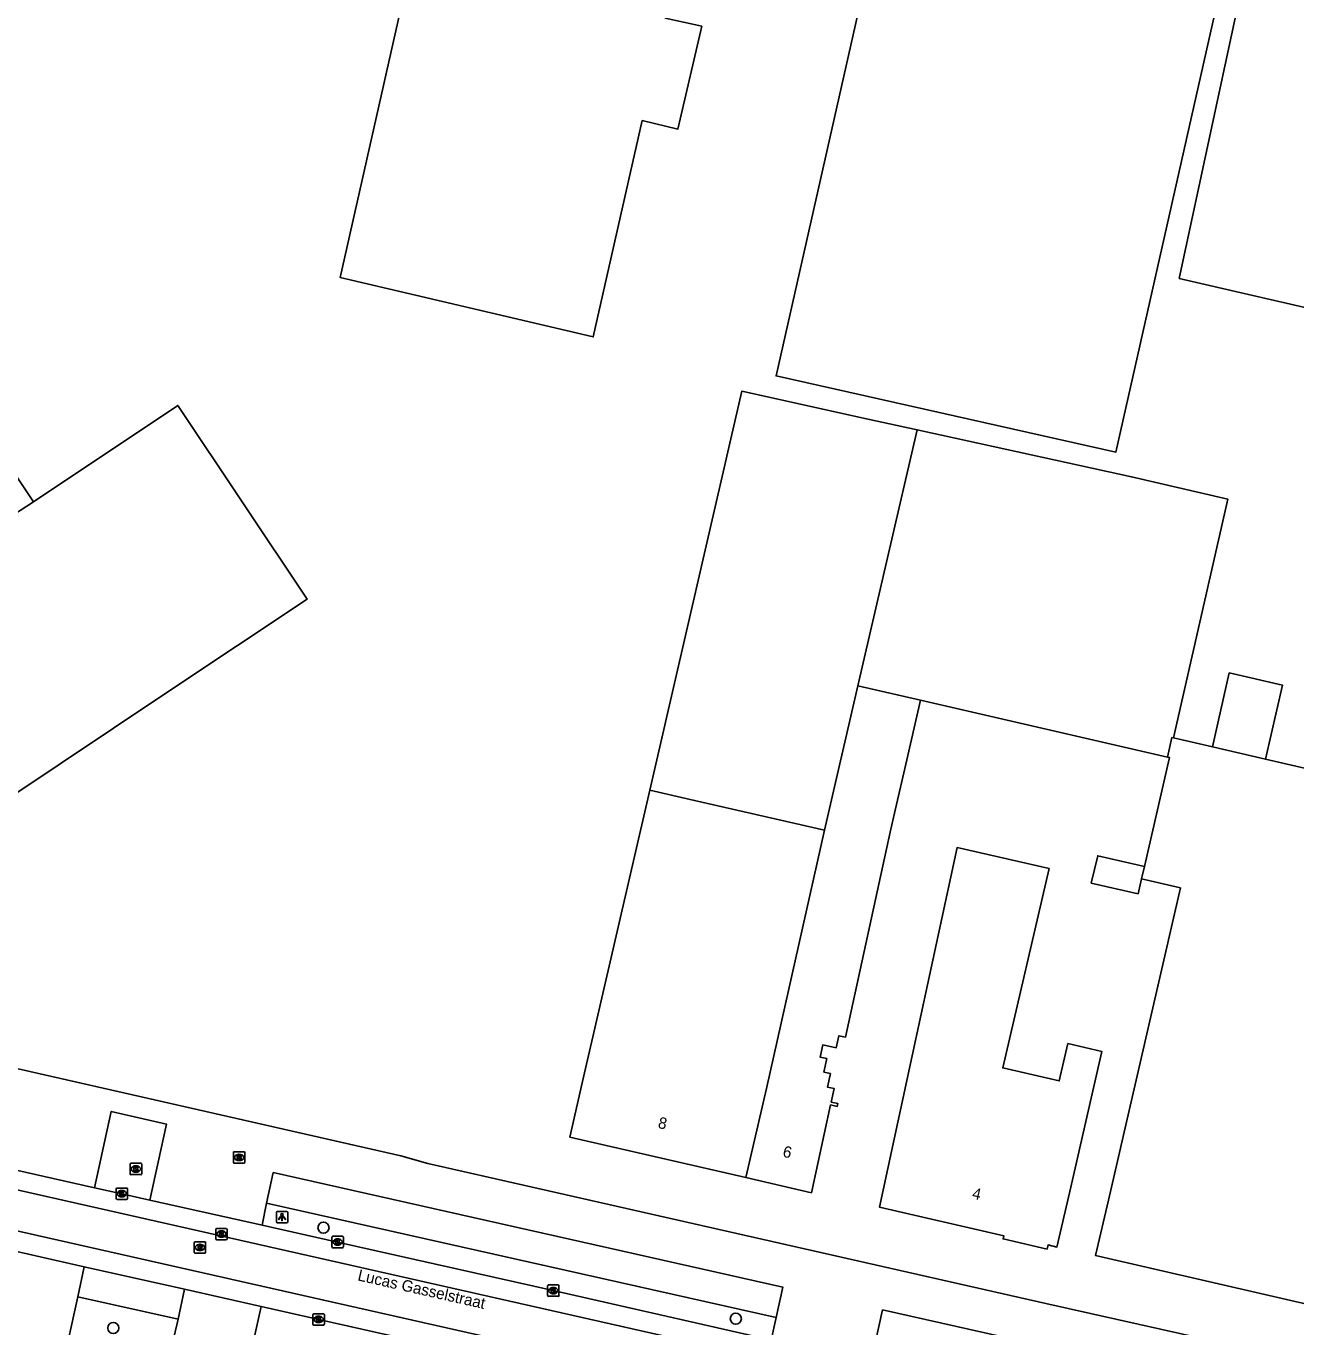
# Model space of a CAD drawing. Extents: x 161771 to 163125, y 382479 to 383177.
# Drawn here: x 162363.8 to 162475.6, y 382859.4 to 382973.9 of the extents above; entities that cross this region are included whole.
import ezdxf

# ---------------------------------------------------------------- set-up
doc = ezdxf.new("R2010")
doc.units = 0
for name, color, linetype in [('IMGEO_Boom', 7, 'Continuous'), ('IMGEO_Kolk', 7, 'Continuous'), ('IMGEO_Lichtpunt', 7, 'Continuous'), ('IMGEO_Openbare_ruimte_label', 7, 'Continuous'), ('IMGEO_Pand', 7, 'Continuous'), ('IMGEO_Pand_nummerreeks', 7, 'Continuous'), ('IMGEO_Parkeervlak_open', 7, 'Continuous'), ('IMGEO_Rijbaan_lokaal_gesloten', 7, 'Continuous'), ('IMGEO_Rioolput', 7, 'Continuous'), ('IMGEO_Voetpad_open', 7, 'Continuous')]:
    doc.layers.add(name, color=color, linetype=linetype)

msp = doc.modelspace()

# ---------------------------------------------------------------- linework, layer by layer
at = {"layer": 'IMGEO_Boom'}
for centre in [(162389.99, 382868.18), (162371.49, 382859.35), (162426.28, 382860.17)]:
    msp.add_circle(centre, 0.489, dxfattribs=at)
at = {"layer": 'IMGEO_Kolk'}
for p, q in [((162372.99, 382872.92), (162372.99, 382873.77)), ((162373.06, 382873.85), (162373.91, 382873.85)), ((162373.47, 382873.63), (162373.5, 382873.63)), ((162373.99, 382873.77), (162373.99, 382872.92)), ((162373.91, 382872.85), (162373.06, 382872.85)), ((162373.5, 382873.07), (162373.47, 382873.07)), ((162371.74, 382870.74), (162371.74, 382871.6)), ((162371.82, 382871.67), (162372.67, 382871.67)), ((162372.23, 382871.45), (162372.25, 382871.45)), ((162372.74, 382871.6), (162372.74, 382870.74)), ((162372.67, 382870.67), (162371.82, 382870.67)), ((162372.25, 382870.89), (162372.23, 382870.89)), ((162390.74, 382866.49), (162390.74, 382867.34)), ((162390.81, 382867.42), (162391.67, 382867.42)), ((162391.23, 382867.2), (162391.25, 382867.2)), ((162391.25, 382866.64), (162391.23, 382866.64)), ((162391.74, 382867.34), (162391.74, 382866.49)), ((162391.67, 382866.42), (162390.81, 382866.42)), ((162409.8, 382863.14), (162410.65, 382863.14)), ((162409.72, 382862.21), (162409.72, 382863.06)), ((162410.65, 382862.14), (162409.8, 382862.14)), ((162410.21, 382862.92), (162410.23, 382862.92)), ((162410.23, 382862.36), (162410.21, 382862.36)), ((162410.72, 382863.06), (162410.72, 382862.21)), ((162389.06, 382859.68), (162389.06, 382860.53)), ((162389.14, 382860.61), (162389.99, 382860.61)), ((162389.55, 382860.39), (162389.58, 382860.39)), ((162389.57, 382859.83), (162389.55, 382859.83)), ((162390.07, 382860.53), (162390.07, 382859.68)), ((162389.99, 382859.61), (162389.14, 382859.61))]:
    msp.add_line(p, q, dxfattribs=at)
for points in [[(162372.99, 382872.92), (162372.99, 382873.77)], [(162373.06, 382873.85), (162373.91, 382873.85)], [(162373.31, 382873.55), (162373.43, 382873.55), (162373.43, 382873.39), (162373.56, 382873.55), (162373.72, 382873.55), (162373.58, 382873.4), (162373.73, 382873.15), (162373.58, 382873.15), (162373.49, 382873.31), (162373.43, 382873.24), (162373.43, 382873.15), (162373.31, 382873.15), (162373.31, 382873.55)], [(162373.99, 382873.77), (162373.99, 382872.92)], [(162373.91, 382872.85), (162373.06, 382872.85)], [(162371.74, 382870.74), (162371.74, 382871.6)], [(162371.82, 382871.67), (162372.67, 382871.67)], [(162372.06, 382871.37), (162372.19, 382871.37), (162372.19, 382871.22), (162372.31, 382871.37), (162372.48, 382871.37), (162372.33, 382871.22), (162372.49, 382870.97), (162372.33, 382870.97), (162372.25, 382871.14), (162372.19, 382871.07), (162372.19, 382870.97), (162372.06, 382870.97), (162372.06, 382871.37)], [(162372.74, 382871.6), (162372.74, 382870.74)], [(162372.67, 382870.67), (162371.82, 382870.67)], [(162390.74, 382866.49), (162390.74, 382867.34)], [(162390.81, 382867.42), (162391.67, 382867.42)], [(162391.06, 382867.12), (162391.18, 382867.12), (162391.18, 382866.96), (162391.31, 382867.12), (162391.48, 382867.12), (162391.33, 382866.97), (162391.48, 382866.72), (162391.33, 382866.72), (162391.25, 382866.88), (162391.18, 382866.81), (162391.18, 382866.72), (162391.06, 382866.72), (162391.06, 382867.12)], [(162391.74, 382867.34), (162391.74, 382866.49)], [(162391.67, 382866.42), (162390.81, 382866.42)], [(162409.8, 382863.14), (162410.65, 382863.14)], [(162409.72, 382862.21), (162409.72, 382863.06)], [(162410.65, 382862.14), (162409.8, 382862.14)], [(162410.04, 382862.84), (162410.17, 382862.84), (162410.17, 382862.69), (162410.29, 382862.84), (162410.46, 382862.84), (162410.31, 382862.69), (162410.47, 382862.44), (162410.31, 382862.44), (162410.23, 382862.6), (162410.17, 382862.53), (162410.17, 382862.44), (162410.04, 382862.44), (162410.04, 382862.84)], [(162410.72, 382863.06), (162410.72, 382862.21)], [(162389.06, 382859.68), (162389.06, 382860.53)], [(162389.14, 382860.61), (162389.99, 382860.61)], [(162389.38, 382860.31), (162389.51, 382860.31), (162389.51, 382860.15), (162389.64, 382860.31), (162389.8, 382860.31), (162389.66, 382860.16), (162389.81, 382859.91), (162389.66, 382859.91), (162389.57, 382860.07), (162389.51, 382860), (162389.51, 382859.91), (162389.38, 382859.91), (162389.38, 382860.31)], [(162390.07, 382860.53), (162390.07, 382859.68)], [(162389.99, 382859.61), (162389.14, 382859.61)]]:
    msp.add_lwpolyline(points, dxfattribs=at)
for centre, start, end in [((162373.06, 382873.77), 91.552, 178.448), ((162373.06, 382873.77), 91.552, 178.448), ((162373.91, 382873.77), 1.552, 88.448), ((162373.91, 382873.77), 1.552, 88.448), ((162373.06, 382872.92), 181.552, 268.448), ((162373.06, 382872.92), 181.552, 268.448), ((162373.91, 382872.92), 271.552, 358.448), ((162373.91, 382872.92), 271.552, 358.448), ((162371.82, 382871.6), 91.552, 178.448), ((162371.82, 382871.6), 91.552, 178.448), ((162372.67, 382871.6), 1.552, 88.448), ((162372.67, 382871.6), 1.552, 88.448), ((162371.82, 382870.75), 181.552, 268.448), ((162371.82, 382870.75), 181.552, 268.448), ((162372.67, 382870.75), 271.552, 358.448), ((162372.67, 382870.75), 271.552, 358.448), ((162390.82, 382867.34), 91.552, 178.448), ((162390.82, 382867.34), 91.552, 178.448), ((162391.66, 382867.34), 1.552, 88.448), ((162391.66, 382867.34), 1.552, 88.448), ((162390.82, 382866.49), 181.552, 268.448), ((162390.82, 382866.49), 181.552, 268.448), ((162391.66, 382866.49), 271.552, 358.448), ((162391.66, 382866.49), 271.552, 358.448), ((162409.8, 382863.06), 91.552, 178.448), ((162409.8, 382863.06), 91.552, 178.448), ((162410.65, 382863.06), 1.552, 88.448), ((162410.65, 382863.06), 1.552, 88.448), ((162409.8, 382862.21), 181.552, 268.448), ((162409.8, 382862.21), 181.552, 268.448), ((162410.65, 382862.21), 271.552, 358.448), ((162410.65, 382862.21), 271.552, 358.448), ((162389.14, 382860.53), 91.552, 178.448), ((162389.14, 382860.53), 91.552, 178.448), ((162389.14, 382859.68), 181.552, 268.448), ((162389.14, 382859.68), 181.552, 268.448), ((162389.99, 382860.53), 1.552, 88.448), ((162389.99, 382860.53), 1.552, 88.448), ((162389.99, 382859.68), 271.552, 358.448), ((162389.99, 382859.68), 271.552, 358.448)]:
    msp.add_arc(centre, 0.0765, start, end, dxfattribs=at)
for centre, major_axis, ratio, start_param, end_param in [((162373.47, 382873.35), (-0.387, 0.002), 0.722429, 4.712389, 7.853982), ((162373.5, 382873.35), (-0.39, 0.002), 0.717154, 1.570796, 4.712389), ((162372.23, 382871.17), (-0.387, 0.002), 0.722429, 4.712389, 7.853982), ((162372.25, 382871.17), (-0.39, 0.002), 0.717154, 1.570796, 4.712389), ((162391.23, 382866.92), (-0.387, 0.002), 0.722429, 4.712389, 7.853982), ((162391.25, 382866.92), (-0.39, 0.002), 0.717154, 1.570796, 4.712389), ((162410.21, 382862.64), (-0.387, 0.002), 0.722429, 4.712389, 7.853982), ((162410.23, 382862.64), (-0.39, 0.002), 0.717154, 1.570796, 4.712389), ((162389.55, 382860.11), (-0.387, 0.002), 0.722429, 4.712389, 7.853982), ((162389.58, 382860.11), (-0.39, 0.002), 0.717154, 1.570796, 4.712389)]:
    msp.add_ellipse(centre, major_axis=major_axis, ratio=ratio, start_param=start_param, end_param=end_param, dxfattribs=at)
at = {"layer": 'IMGEO_Lichtpunt'}
for p, q in [((162385.85, 382869.52), (162385.85, 382868.71)), ((162385.85, 382869.52), (162385.85, 382868.71)), ((162386.75, 382869.62), (162385.94, 382869.62)), ((162386.75, 382869.62), (162385.94, 382869.62)), ((162386.85, 382868.71), (162386.85, 382869.52)), ((162386.85, 382868.71), (162386.85, 382869.52)), ((162385.94, 382868.62), (162386.75, 382868.62)), ((162385.94, 382868.62), (162386.75, 382868.62))]:
    msp.add_line(p, q, dxfattribs=at)
for points in [[(162386.22, 382869.18), (162386.26, 382869.16), (162386.07, 382868.89), (162386.04, 382868.92), (162386.22, 382869.18)], [(162386.32, 382869.14), (162386.37, 382869.14), (162386.37, 382868.81), (162386.32, 382868.81), (162386.32, 382869.14)], [(162386.43, 382869.16), (162386.47, 382869.18), (162386.66, 382868.92), (162386.62, 382868.89), (162386.43, 382869.16)]]:
    msp.add_lwpolyline(points, dxfattribs=at)
msp.add_circle((162386.35, 382869.32), 0.0994, dxfattribs=at)
for centre, start, end in [((162385.94, 382869.52), 90, 180), ((162385.94, 382869.52), 90, 180), ((162386.75, 382869.52), 0, 90), ((162386.75, 382869.52), 0, 90), ((162385.94, 382868.71), 180, 270), ((162385.94, 382868.71), 180, 270), ((162386.75, 382868.71), 270, 0), ((162386.75, 382868.71), 270, 360)]:
    msp.add_arc(centre, 0.0946, start, end, dxfattribs=at)
at = {"layer": 'IMGEO_Pand'}
for points in [[(162427.74, 383000.41), (162426.87, 382996.7), (162425.17, 382997.1), (162420.34, 382975.79), (162420.07, 382974.64), (162423.28, 382973.91), (162421.18, 382964.87), (162418.05, 382965.61), (162413.73, 382946.58), (162391.46, 382951.81), (162400.65, 382992.52), (162403.25, 382991.93), (162402.89, 382990.34), (162418.4, 382986.84), (162421.3, 382999.68), (162424.89, 382998.86), (162424.99, 382999.26), (162425.37, 383000.91)], [(162470.51, 382991.08), (162469.41, 382986.14), (162470.87, 382985.85), (162459.74, 382936.44), (162429.83, 382943.14), (162441.13, 382993.19), (162444.44, 382992.42), (162445.17, 382995.46), (162446.64, 382995.17), (162446.92, 382996.39)], [(162525.72, 382978.26), (162520.64, 382955.82), (162498.45, 382960.84), (162497.41, 382956.34), (162485.74, 382959.03), (162483.11, 382947.62), (162465.31, 382951.72), (162471.68, 382981.36), (162471.87, 382981.32), (162477.88, 382979.93)], [(162338.5, 382915.18), (162328.22, 382932.53), (162353.13, 382949.04), (162364.46, 382932.07)], [(162418.71, 382906.68), (162426.8, 382941.79), (162438.06, 382939.32), (162442.24, 382938.4)], [(162364.46, 382932.07), (162377.17, 382940.55), (162388.55, 382923.49), (162376.12, 382915.21), (162352.87, 382899.71), (162350.05, 382897.83), (162348.8, 382899.71), (162338.69, 382914.86), (162338.5, 382915.18)], [(162437.02, 382915.88), (162442.24, 382938.4)], [(162442.24, 382938.4), (162461.11, 382934.27), (162469.58, 382932.31), (162464.8, 382911.28)], [(162364.46, 382932.07), (162338.5, 382915.18)], [(162472.91, 382909.42), (162474.39, 382915.94), (162469.71, 382917.01), (162468.23, 382910.49)], [(162437.02, 382915.88), (162434.08, 382903.17)], [(162442.53, 382914.61), (162437.02, 382915.88)], [(162442.53, 382914.61), (162441.42, 382909.74), (162440.17, 382904.28), (162439.87, 382902.98), (162435.93, 382884.96), (162435.35, 382885.08), (162435.12, 382884.02), (162433.94, 382884.27), (162433.7, 382883.19), (162434.29, 382883.06), (162434.03, 382881.87), (162434.61, 382881.74), (162434.35, 382880.55), (162434.94, 382880.42), (162434.68, 382879.23), (162435.27, 382879.1), (162435.21, 382878.86), (162434.63, 382878.99), (162432.94, 382871.26), (162427.17, 382872.59)], [(162464.28, 382909.6), (162442.53, 382914.61)], [(162464.8, 382911.28), (162464.67, 382911.31), (162464.28, 382909.6)], [(162468.23, 382910.49), (162464.8, 382911.28)], [(162468.23, 382910.49), (162472.91, 382909.42)], [(162461.99, 382898.88), (162465.41, 382898.09), (162459.08, 382870.6), (162457.95, 382865.73), (162498.57, 382856.37), (162500, 382862.8), (162508.56, 382901.23), (162503.68, 382902.33), (162500, 382903.18), (162472.91, 382909.42)], [(162464.28, 382909.6), (162464.46, 382909.56), (162462.24, 382899.97)], [(162427.17, 382872.59), (162411.68, 382876.16), (162412.8, 382881.04), (162418.71, 382906.68)], [(162434.08, 382903.17), (162422.66, 382905.78), (162418.71, 382906.68)], [(162434.08, 382903.17), (162428.98, 382880.42), (162427.17, 382872.59)], [(162453.85, 382899.78), (162449.78, 382882.24), (162454.75, 382881.1), (162455.51, 382884.38), (162458.51, 382883.68), (162455.67, 382871.36), (162454.55, 382866.48), (162453.76, 382866.67), (162453.68, 382866.3), (162449.81, 382867.19), (162449.87, 382867.47), (162438.92, 382869.99), (162439.98, 382874.88), (162445.76, 382901.63), (162453.85, 382899.78)], [(162461.99, 382898.88), (162461.69, 382897.57), (162457.57, 382898.51), (162458.13, 382900.91), (162462.24, 382899.97)], [(162462.24, 382899.97), (162461.99, 382898.88)]]:
    msp.add_lwpolyline(points, dxfattribs=at)
at = {"layer": 'IMGEO_Parkeervlak_open'}
for points in [[(162384.98, 382870.35), (162429.82, 382860.29)], [(162377.19, 382860.12), (162368.36, 382862.09)]]:
    msp.add_lwpolyline(points, dxfattribs=at)
at = {"layer": 'IMGEO_Rijbaan_lokaal_gesloten'}
for points in [[(162369.84, 382871.7), (162360.06, 382873.9), (162359.13, 382874.16)], [(162522.17, 382835.64), (162521.01, 382835.9), (162466.66, 382848.1), (162359.48, 382872.3)], [(162374.72, 382870.6), (162372.24, 382871.17), (162369.84, 382871.7)], [(162384.59, 382868.39), (162374.72, 382870.6)], [(162521.18, 382832.27), (162495.04, 382838.14), (162484.83, 382840.43), (162390.02, 382861.8), (162355.96, 382869.49)], [(162429.38, 382858.29), (162427.26, 382858.79), (162410.22, 382862.64), (162391.24, 382866.92), (162384.59, 382868.39)], [(162360.78, 382866.57), (162368.94, 382864.74)], [(162368.94, 382864.74), (162377.77, 382862.76)], [(162377.77, 382862.76), (162384.5, 382861.24)], [(162384.5, 382861.24), (162389.57, 382860.11), (162408.51, 382855.84), (162414.43, 382854.5)]]:
    msp.add_lwpolyline(points, dxfattribs=at)
at = {"layer": 'IMGEO_Rioolput'}
for p, q in [((162382.07, 382873.94), (162382.07, 382874.79)), ((162382.14, 382874.86), (162382.99, 382874.86)), ((162382.55, 382874.64), (162382.58, 382874.64)), ((162383.07, 382874.79), (162383.07, 382873.94)), ((162382.99, 382873.86), (162382.14, 382873.86)), ((162382.58, 382874.08), (162382.55, 382874.08)), ((162380.51, 382867.19), (162380.51, 382868.04)), ((162380.59, 382868.12), (162381.44, 382868.12)), ((162381, 382867.9), (162381.02, 382867.9)), ((162381.51, 382868.04), (162381.51, 382867.19)), ((162378.62, 382866.01), (162378.62, 382866.86)), ((162378.7, 382866.94), (162379.55, 382866.94)), ((162379.11, 382866.72), (162379.13, 382866.72)), ((162379.62, 382866.86), (162379.62, 382866.01)), ((162381.44, 382867.12), (162380.59, 382867.12)), ((162381.02, 382867.34), (162381, 382867.34)), ((162379.55, 382865.94), (162378.7, 382865.94)), ((162379.13, 382866.16), (162379.11, 382866.16))]:
    msp.add_line(p, q, dxfattribs=at)
for points in [[(162382.07, 382873.94), (162382.07, 382874.79)], [(162382.14, 382874.86), (162382.99, 382874.86)], [(162382.65, 382874.56), (162382.4, 382874.56), (162382.4, 382874.16)], [(162383.07, 382874.79), (162383.07, 382873.94)], [(162382.99, 382873.86), (162382.14, 382873.86)], [(162382.4, 382874.16), (162382.53, 382874.16), (162382.53, 382874.32), (162382.54, 382874.32)], [(162382.58, 382874.48), (162382.53, 382874.48), (162382.53, 382874.4)], [(162382.53, 382874.4), (162382.58, 382874.4)], [(162382.58, 382874.29), (162382.66, 382874.16), (162382.79, 382874.16), (162382.73, 382874.29)], [(162380.51, 382867.19), (162380.51, 382868.04)], [(162380.59, 382868.12), (162381.44, 382868.12)], [(162381.1, 382867.81), (162380.85, 382867.82), (162380.85, 382867.42)], [(162381.03, 382867.74), (162380.97, 382867.74), (162380.97, 382867.65)], [(162380.97, 382867.65), (162381.02, 382867.65)], [(162381.51, 382868.04), (162381.51, 382867.19)], [(162378.62, 382866.01), (162378.62, 382866.86)], [(162378.7, 382866.94), (162379.55, 382866.94)], [(162379.21, 382866.63), (162378.96, 382866.64), (162378.96, 382866.24)], [(162379.14, 382866.56), (162379.08, 382866.56), (162379.08, 382866.47)], [(162379.62, 382866.86), (162379.62, 382866.01)], [(162381.44, 382867.12), (162380.59, 382867.12)], [(162380.85, 382867.42), (162380.97, 382867.42), (162380.97, 382867.58), (162380.98, 382867.58)], [(162381.03, 382867.55), (162381.1, 382867.42), (162381.24, 382867.42), (162381.18, 382867.54)], [(162379.55, 382865.94), (162378.7, 382865.94)], [(162378.96, 382866.24), (162379.08, 382866.24), (162379.08, 382866.4), (162379.09, 382866.4)], [(162379.08, 382866.47), (162379.13, 382866.47)], [(162379.14, 382866.37), (162379.21, 382866.24), (162379.35, 382866.24), (162379.29, 382866.36)]]:
    msp.add_lwpolyline(points, dxfattribs=at)
for centre, radius, start, end in [((162382.14, 382874.79), 0.0765, 91.552, 178.448), ((162382.14, 382874.79), 0.0765, 91.552, 178.448), ((162382.65, 382874.45), 0.109, 350.3612, 89.416), ((162382.99, 382874.79), 0.0765, 1.552, 88.448), ((162382.99, 382874.79), 0.0765, 1.552, 88.448), ((162382.14, 382873.94), 0.0765, 181.552, 268.448), ((162382.14, 382873.94), 0.0765, 181.552, 268.448), ((162382.54, 382874.27), 0.0533, 26.0293, 88.6989), ((162382.59, 382874.38), 0.0964, 77.0061, 93.1865), ((162382.56, 382874.59), 0.19, 274.7715, 282.9687), ((162382.6, 382874.44), 0.0378, 276.6634, 79.6772), ((162382.65, 382874.45), 0.112, 277.5842, 350.9817), ((162382.64, 382874.23), 0.108, 29.5134, 73.7905), ((162382.99, 382873.94), 0.0765, 271.552, 358.448), ((162382.99, 382873.94), 0.0765, 271.552, 358.448), ((162380.59, 382868.04), 0.0765, 91.552, 178.448), ((162380.59, 382868.04), 0.0765, 91.552, 178.448), ((162381.01, 382867.84), 0.19, 274.7715, 282.9687), ((162381.03, 382867.64), 0.0964, 77.0061, 93.1865), ((162381.05, 382867.7), 0.0378, 276.6634, 79.6772), ((162381.1, 382867.71), 0.109, 350.3612, 89.416), ((162381.1, 382867.7), 0.112, 277.5842, 350.9817), ((162381.44, 382868.04), 0.0765, 1.552, 88.448), ((162381.44, 382868.04), 0.0765, 1.552, 88.448), ((162378.7, 382866.86), 0.0765, 91.552, 178.448), ((162378.7, 382866.86), 0.0765, 91.552, 178.448), ((162379.14, 382866.46), 0.0964, 77.0061, 93.1865), ((162379.16, 382866.52), 0.0378, 276.6634, 79.6772), ((162379.21, 382866.52), 0.109, 350.3612, 89.416), ((162379.21, 382866.52), 0.112, 277.5842, 350.9817), ((162379.55, 382866.86), 0.0765, 1.552, 88.448), ((162379.55, 382866.86), 0.0765, 1.552, 88.448), ((162380.59, 382867.19), 0.0765, 181.552, 268.448), ((162380.59, 382867.19), 0.0765, 181.552, 268.448), ((162380.98, 382867.53), 0.0533, 26.0293, 88.6989), ((162381.08, 382867.49), 0.108, 29.5134, 73.7905), ((162381.44, 382867.19), 0.0765, 271.552, 358.448), ((162381.44, 382867.19), 0.0765, 271.552, 358.448), ((162378.7, 382866.01), 0.0765, 181.552, 268.448), ((162378.7, 382866.01), 0.0765, 181.552, 268.448), ((162379.09, 382866.35), 0.0533, 26.0293, 88.6989), ((162379.12, 382866.66), 0.19, 274.7715, 282.9687), ((162379.19, 382866.31), 0.108, 29.5134, 73.7905), ((162379.55, 382866.01), 0.0765, 271.552, 358.448), ((162379.55, 382866.01), 0.0765, 271.552, 358.448)]:
    msp.add_arc(centre, radius, start, end, dxfattribs=at)
for centre, major_axis, ratio, start_param, end_param in [((162382.55, 382874.36), (-0.387, 0.002), 0.722429, 4.712389, 7.853982), ((162382.58, 382874.36), (-0.39, 0.002), 0.717154, 1.570796, 4.712389), ((162381, 382867.62), (-0.387, 0.002), 0.722429, 4.712389, 7.853982), ((162381.02, 382867.62), (-0.39, 0.002), 0.717154, 1.570796, 4.712389), ((162379.11, 382866.44), (-0.387, 0.002), 0.722429, 4.712389, 7.853982), ((162379.13, 382866.44), (-0.39, 0.002), 0.717154, 1.570796, 4.712389)]:
    msp.add_ellipse(centre, major_axis=major_axis, ratio=ratio, start_param=start_param, end_param=end_param, dxfattribs=at)
at = {"layer": 'IMGEO_Voetpad_open'}
for points in [[(162350.42, 382884.99), (162352.76, 382884.51), (162396.81, 382874.5), (162399.17, 382873.84), (162426.37, 382867.67), (162453.57, 382861.51), (162499.82, 382851.14), (162502.64, 382852.09), (162505.56, 382864.95)], [(162369.84, 382871.7), (162371.32, 382878.42), (162376.19, 382877.28), (162374.72, 382870.6)], [(162384.98, 382870.35), (162385.57, 382873.03), (162430.43, 382862.94), (162429.82, 382860.29)], [(162384.59, 382868.39), (162384.98, 382870.35)], [(162368.36, 382862.09), (162368.94, 382864.74)], [(162377.19, 382860.12), (162376.7, 382858.02), (162376.3, 382856.26), (162367.52, 382858.25), (162368.36, 382862.09)], [(162377.77, 382862.76), (162377.19, 382860.12)], [(162383.93, 382858.59), (162384.5, 382861.24)], [(162438.6, 382858.28), (162439.2, 382860.95), (162491.8, 382849.13), (162491.19, 382846.45)], [(162429.82, 382860.29), (162429.38, 382858.29)]]:
    msp.add_lwpolyline(points, dxfattribs=at)

# ---------------------------------------------------------------- texts
at = {"layer": 'IMGEO_Openbare_ruimte_label'}
msp.add_text('Lucas Gasselstraat', height=1, rotation=347.2288, dxfattribs=at).set_placement((162392.94, 382863.55))
at = {"layer": 'IMGEO_Pand_nummerreeks'}
for s, rotation, p in [('8', 347.0186, (162419.37, 382876.98)), ('6', 347.0206, (162430.35, 382874.44)), ('4', 347.3575, (162447.02, 382870.76))]:
    msp.add_text(s, height=1, rotation=rotation, dxfattribs=at).set_placement(p)

doc.saveas('drawing.dxf')
